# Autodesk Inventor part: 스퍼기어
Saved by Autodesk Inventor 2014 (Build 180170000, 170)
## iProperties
Created: 2026-03
Part Number: 스퍼기어
Material: 일반
Document SubType Name: Modeling
Designer: dg
Density: 1 g/cm^3
Appearance: 기본값
Mass: 23.1052 g
Surface Area: 82.8661 cm^2
Volume: 23.1052 cm^3
Author: jhkim
Creation Date: 2025-06-27
Sending System: Autodesk Inventor 2026
Preprocessor: ST-DEVELOPER v20.1
Author: dg
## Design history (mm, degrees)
node "스퍼기어1"
node "솔리드1"
node "기준1"
